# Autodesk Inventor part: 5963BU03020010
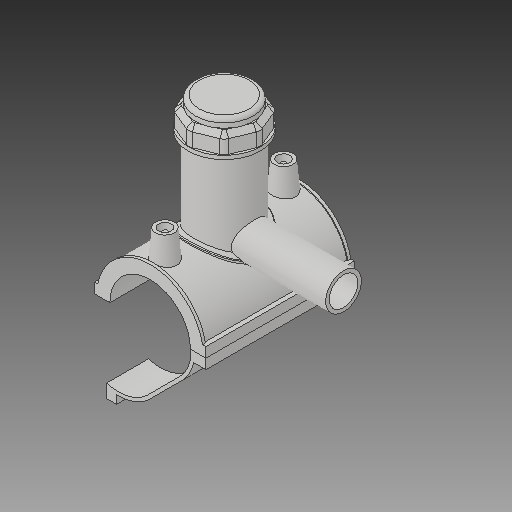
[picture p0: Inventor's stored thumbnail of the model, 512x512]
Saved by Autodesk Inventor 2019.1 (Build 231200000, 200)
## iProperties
Created: 2017-07
Part Number: 5963BU03020010
Material: Generic
Description: PLASSON TAPPING SADDLE 2''IPS x 1''CTS
Document SubType Name: Modeling
Designer: KIM
Mass: 1712.7 g
Surface Area: 2671.49 cm^2
Volume: 1712.7 cm^3
Density: 1 g/cm^3
Appearance: Default
Author: KIM
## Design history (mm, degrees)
derived "5963B.ipt"
feature "Solid1::5963B.ipt"
feature "Solid2::5963B.ipt"
feature "Solid4::5963B.ipt"
feature "Solid5::5963B.ipt"
tag "TaggingFeature1"
body "Solid1"
body "Solid2"
other parameters: "d0" = 64.1, "d2" = 88.9, "d3" = 16.025, "d4" = 118.11, "d5" = 0, "d6" = 0.1, "d8" = 0, "d19" = 6, "d20" = 6, "d21" = 70.866, "d23" = 0, "d24" = 35.433, "d26" = 0, "d29" = 3, "d30" = 21.36667, "d31" = 6, "d32" = 0, "d33" = 0, "d34" = 0.6, "d40" = 43.3316, "d41" = 57.69, "d43" = 0, "d45" = 0, "d47" = 112.531, "d70" = 15, "d72" = 0, "d73" = 6, "d75" = 5, "d76" = 0, "d77" = 3.205, "d78" = 62.05, "d79" = 15, "d80" = 47.244, "d82" = 5 deg, "d84" = 4, "d85" = 14, "d86" = 0, "d87" = 3, "d88" = 0, "d89" = 1, "d90" = 1, "d91" = 94.488, "d92" = 0, "d93" = 0.5, "d94" = 33.73684, "d96" = 84.9966, "d97" = 2.3622, "d98" = 0, "d102" = 0.641, "d120" = 140 deg, "d121" = 24.228, "d122" = 20 deg, "d123" = 166.66, "d124" = 49.998, "d126" = 0, "d143" = 66.023, "d145" = 14.79231, "d149" = 0.9615, "d150" = 16.27154, "d153" = 118.11, "d154" = 0, "d156" = 41.665, "d157" = 160 deg, "d159" = 3.846, "d161" = 0.9615, "d162" = 70.866, "d163" = 0, "d164" = 32.05, "d167" = 6.41, "d168" = 40.64878, "d170" = 3.2805, "d172" = 0, "d173" = 1, "d175" = 32.05, "d176" = 20 deg, "d177" = 4.487, "d178" = 19.23, "d180" = 0, "d183" = 7.692, "d184" = 3.5896, "d185" = 38.38575, "d186" = 38.38575, "d187" = 41.665, "d188" = 5.769, "d189" = 4.487, "d190" = 0, "d191" = 62.4975, "d193" = 6.1236, "d194" = 4.13385, "d195" = 90 deg, "d197" = 0, "d199" = 0, "d200" = 9.615, "d202" = 0, "d203" = 98.044, "d204" = 54.8055, "d205" = 40.383, "d206" = 49.0365, "d207" = 73.533, "d208" = 76.47432, "d209" = 91.18092, "d210" = 49.6134, "d211" = 57.69, "d212" = 46.152, "d213" = -3.8871, "d216" = 0, "d217" = 6.41, "d218" = 3.205, "d219" = 0.641, "d222" = 64.1, "d224" = 0, "d230" = 3.846, "d233" = 6, "d236" = 44.45, "d237" = 35.433, "d238" = 6.02433, "d240" = 35.433, "d241" = 35.433, "d242" = 35.433, "d243" = 6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
